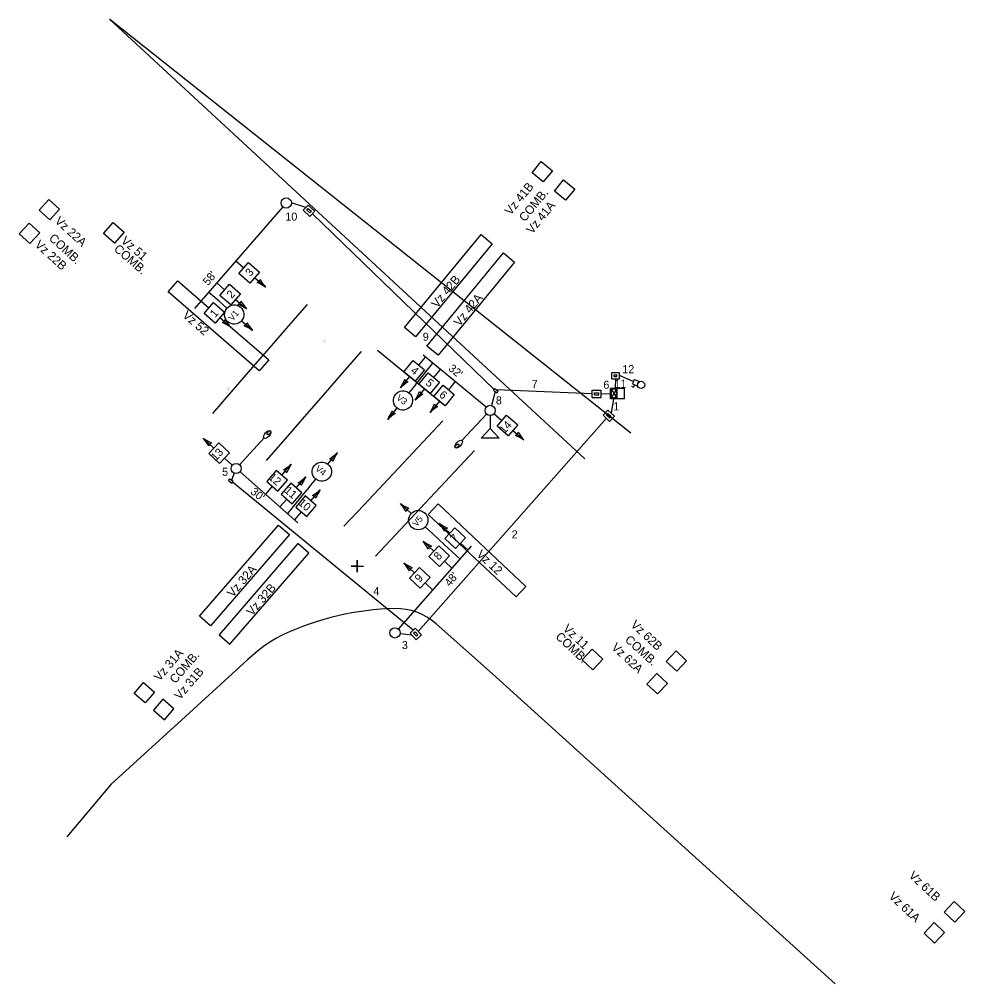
# Model space of a CAD drawing. Extents: x 973817 to 2958182, y 703625 to 1593455.
# Drawn here: x 976455 to 976847, y 705316.5 to 705716.5 of the extents above; entities that cross this region are included whole.
import ezdxf

# ---------------------------------------------------------------- set-up
doc = ezdxf.new("R2010")
doc.units = 0
for name, color, linetype in [('R_Fin Surface', 7, 'Continuous'), ('S_EDGE_PAVEMENT', 7, 'Continuous'), ('S_PAVEMENT_CROWN', 7, 'Continuous'), ('T_Conduit', 7, 'Continuous'), ('T_Detection Annot', 7, 'Continuous'), ('T_Detection Zones', 7, 'Continuous'), ('T_Drafting', 7, 'Continuous'), ('T_Indications', 7, 'Continuous'), ('T_Mast Arm', 7, 'Continuous')]:
    doc.layers.add(name, color=color, linetype=linetype)

msp = doc.modelspace()

# ---------------------------------------------------------------- linework, layer by layer
at = {"layer": 'R_Fin Surface'}
for p, q in [((976566.66, 705589.15), (976574.54, 705598.21)), ((976558.79, 705580.1), (976566.66, 705589.15)), ((976550.92, 705571.04), (976558.79, 705580.1)), ((976589.03, 705569.7), (976596.9, 705578.76)), ((976612.77, 705571.52), (976603.5, 705579.14)), ((976543.04, 705561.98), (976550.92, 705571.04)), ((976622.04, 705563.9), (976612.77, 705571.52)), ((976581.16, 705560.65), (976589.03, 705569.7)), ((976631.31, 705556.28), (976622.04, 705563.9)), ((976535.17, 705552.93), (976543.04, 705561.98)), ((976573.28, 705551.59), (976581.16, 705560.65)), ((976565.41, 705542.54), (976573.28, 705551.59)), ((976622.42, 705541.2), (976630.64, 705549.95)), ((976557.53, 705533.48), (976565.41, 705542.54)), ((976614.21, 705532.45), (976622.42, 705541.2)), ((976635.56, 705528.87), (976643.77, 705537.62)), ((976606, 705523.7), (976614.21, 705532.45)), ((976627.35, 705520.12), (976635.56, 705528.87)), ((976597.78, 705514.95), (976606, 705523.7)), ((976619.13, 705511.37), (976627.35, 705520.12)), ((976589.57, 705506.2), (976597.78, 705514.95)), ((976610.92, 705502.62), (976619.13, 705511.37)), ((976602.71, 705493.87), (976610.92, 705502.62))]:
    msp.add_line(p, q, dxfattribs=at)
for points in [[(976627.79, 705465.8), (976651.26, 705445.05), (976793.32, 705316.53)], [(976553.78, 705454.43), (976549.69, 705451), (976523.84, 705427.4), (976492.98, 705399.12), (976474.69, 705377.5)]]:
    msp.add_lwpolyline(points, dxfattribs=at)
for centre, radius, start, end in [((976613.14, 705357.1), 115, 91.2175, 115.0085), ((976611.23, 705447.08), 25, 48.5105, 91.2175), ((976585.9, 705416.11), 50, 115.3067, 129.9723)]:
    msp.add_arc(centre, radius, start, end, dxfattribs=at)
at = {"layer": 'S_EDGE_PAVEMENT'}
msp.add_lwpolyline([(976595.14, 705489.73), (976595.14, 705492.23), (976595.14, 705489.73), (976592.64, 705489.73), (976595.14, 705489.73), (976595.14, 705487.23), (976595.14, 705489.73), (976597.64, 705489.73)], dxfattribs=at)
at = {"layer": 'S_PAVEMENT_CROWN'}
for p, q in [((976492.45, 705716.47), (976689.49, 705534.24)), ((976708.53, 705544.9), (976492.53, 705716.4))]:
    msp.add_line(p, q, dxfattribs=at)
at = {"layer": 'T_Conduit'}
for p, q in [((976573.74, 705638.36), (976567.82, 705640.3)), ((976651.89, 705562.99), (976576.5, 705635.82)), ((976702.22, 705567.32), (976701.99, 705563.42)), ((976709.58, 705566.21), (976703.81, 705568.68)), ((976692.51, 705561.21), (976652.86, 705562.82)), ((976652.35, 705562.06), (976650.72, 705556.33)), ((976696.26, 705561.15), (976700.15, 705561.25)), ((976701.4, 705559.09), (976700.36, 705553.14)), ((976698.39, 705550.99), (976620.36, 705462.59)), ((976544.15, 705528.18), (976543.03, 705525.4)), ((976618.28, 705463.11), (976543.43, 705524.51)), ((976617.81, 705461.03), (976612.86, 705461.64))]:
    msp.add_line(p, q, dxfattribs=at)
at = {"layer": 'T_Detection Zones'}
for points in [[(976672.21, 705649.03), (976667.57, 705652.84), (976671.38, 705657.47), (976676.02, 705653.66)], [(976681.49, 705641.42), (976676.85, 705645.23), (976680.66, 705649.86), (976685.3, 705646.05)], [(976471.72, 705637.67), (976467.68, 705633.24), (976463.24, 705637.28), (976467.28, 705641.71)], [(976463.47, 705627.87), (976459.43, 705623.43), (976454.99, 705627.47), (976459.03, 705631.91)], [(976489.94, 705627.61), (976493.88, 705632.14), (976498.41, 705628.2), (976494.47, 705623.67)], [(976614.69, 705588.6), (976646.45, 705627.22), (976651.09, 705623.41), (976619.33, 705584.79)], [(976623.96, 705580.98), (976655.72, 705619.6), (976660.36, 705615.78), (976628.6, 705577.17)], [(976566.98, 705502.82), (976534.32, 705464.96), (976529.77, 705468.89), (976562.44, 705506.74)], [(976570.47, 705499.05), (976537.8, 705461.2), (976542.34, 705457.28), (976575.01, 705495.13)], [(976688.42, 705450.85), (976692.53, 705455.23), (976696.91, 705451.12), (976692.8, 705446.75)], [(976723.21, 705450.18), (976727.32, 705454.55), (976731.69, 705450.44), (976727.59, 705446.07)], [(976715.23, 705440.79), (976719.34, 705445.17), (976723.71, 705441.06), (976719.61, 705436.69)], [(976506.55, 705441.4), (976511.09, 705437.48), (976507.17, 705432.94), (976502.63, 705436.86)], [(976519.06, 705430.55), (976514.52, 705434.47), (976510.6, 705429.93), (976515.14, 705426.01)], [(976838.5, 705346.18), (976842.6, 705350.55), (976846.98, 705346.44), (976842.87, 705342.07)], [(976830.16, 705337.55), (976834.32, 705341.87), (976838.64, 705337.72), (976834.49, 705333.39)]]:
    msp.add_lwpolyline(points, close=True, dxfattribs=at)
for points in [[(976541.47, 705589.94), (976558.4, 705575.22), (976554.46, 705570.69), (976516.73, 705603.5), (976520.67, 705608.03), (976533.61, 705596.77)], [(976538.19, 705592.8), (976540.42, 705590.86)], [(976633.14, 705503.05), (976624.52, 705511.14), (976628.63, 705515.51), (976665.08, 705481.29), (976660.97, 705476.92), (976633.14, 705503.05)]]:
    msp.add_lwpolyline(points, dxfattribs=at)
at = {"layer": 'T_Drafting'}
for p, q in [((976572.75, 705637.29), (976574.73, 705639.43)), ((976574.73, 705639.43), (976577.49, 705636.9)), ((976572.75, 705637.29), (976575.52, 705634.75)), ((976574.17, 705637.35), (976574.79, 705638.02)), ((976574.17, 705637.35), (976575.46, 705636.16)), ((976574.79, 705638.02), (976576.08, 705636.84)), ((976575.46, 705636.16), (976576.08, 705636.84)), ((976575.52, 705634.75), (976577.49, 705636.9)), ((976648.57, 705555.61), (976622.44, 705577.16)), ((976700.62, 705570.04), (976703.81, 705570.04)), ((976700.62, 705567.32), (976700.62, 705570.04)), ((976700.62, 705567.32), (976703.81, 705567.32)), ((976701.62, 705568.32), (976701.62, 705569.04)), ((976701.62, 705569.04), (976702.81, 705569.04)), ((976701.62, 705568.32), (976702.81, 705568.32)), ((976702.81, 705568.32), (976702.81, 705569.04)), ((976703.81, 705567.32), (976703.81, 705570.04)), ((976709.98, 705567.13), (976709.19, 705565.29)), ((976709.98, 705567.13), (976711.81, 705566.34)), ((976711.81, 705566.34), (976711.03, 705564.5)), ((976651.61, 705562.63), (976652.17, 705563.35)), ((976651.61, 705562.63), (976652.99, 705561.56)), ((976652.17, 705563.35), (976653.55, 705562.28)), ((976652.99, 705561.56), (976653.55, 705562.28)), ((976692.51, 705562.61), (976696.26, 705562.61)), ((976692.51, 705559.69), (976692.51, 705562.61)), ((976696.26, 705559.69), (976696.26, 705562.61)), ((976705.89, 705563.42), (976700.15, 705563.42)), ((976700.15, 705559.09), (976700.15, 705563.42)), ((976700.48, 705559.42), (976700.48, 705563.09)), ((976702.56, 705563.09), (976700.48, 705563.09)), ((976700.48, 705559.44), (976702.56, 705563.09)), ((976700.48, 705563.09), (976702.56, 705559.42)), ((976702.56, 705559.42), (976702.56, 705563.09)), ((976702.89, 705559.09), (976702.89, 705563.42)), ((976705.89, 705559.09), (976705.89, 705563.42)), ((976708.79, 705564.37), (976709.71, 705563.97)), ((976709.19, 705565.29), (976711.03, 705564.5)), ((976710.11, 705564.89), (976709.71, 705563.97)), ((976692.51, 705559.69), (976696.26, 705559.69)), ((976693.51, 705560.69), (976693.51, 705561.61)), ((976693.51, 705561.61), (976695.26, 705561.61)), ((976693.51, 705560.69), (976695.26, 705560.69)), ((976695.26, 705560.69), (976695.26, 705561.61)), ((976705.89, 705559.09), (976700.15, 705559.09)), ((976702.56, 705559.42), (976700.48, 705559.42)), ((976697.01, 705552.26), (976698.98, 705554.41)), ((976698.98, 705554.41), (976701.74, 705551.87)), ((976648.76, 705552.7), (976638.5, 705541.75)), ((976650.26, 705552.12), (976650.26, 705546.77)), ((976697.01, 705552.26), (976699.77, 705549.72)), ((976698.42, 705552.32), (976699.04, 705552.99)), ((976698.42, 705552.32), (976699.71, 705551.14)), ((976699.04, 705552.99), (976700.33, 705551.81)), ((976699.71, 705551.14), (976700.33, 705551.81)), ((976699.77, 705549.72), (976701.74, 705551.87)), ((976646.51, 705542.77), (976650.26, 705546.77)), ((976650.26, 705546.77), (976654.01, 705542.77)), ((976546.36, 705531.74), (976556.47, 705542.83)), ((976654.01, 705542.77), (976646.51, 705542.77)), ((976541.77, 705525.22), (976542.33, 705525.95)), ((976541.77, 705525.22), (976543.15, 705524.15)), ((976542.33, 705525.95), (976543.72, 705524.87)), ((976543.15, 705524.15), (976543.72, 705524.87)), ((976617, 705461.87), (976619.1, 705463.9)), ((976618.41, 705461.85), (976619.07, 705462.48)), ((976619.07, 705462.48), (976620.29, 705461.23)), ((976619.1, 705463.9), (976621.7, 705461.2)), ((976617, 705461.87), (976619.6, 705459.17)), ((976618.41, 705461.85), (976619.63, 705460.59)), ((976619.6, 705459.17), (976621.7, 705461.2)), ((976619.63, 705460.59), (976620.29, 705461.23))]:
    msp.add_line(p, q, dxfattribs=at)
for centre, radius in [((976565.69, 705640.29), 2.13), ((976712.8, 705564.83), 1.5), ((976650.22, 705554.26), 2.13), ((976544.92, 705530.17), 2.13), ((976610.76, 705462), 2.13)]:
    msp.add_circle(centre, radius, dxfattribs=at)
for centre, major_axis in [((976557.81, 705544.3), (1.35, 1.48)), ((976558.49, 705545.04), (-0.674, -0.739)), ((976637.14, 705540.29), (-1.37, -1.46)), ((976636.45, 705539.56), (0.684, 0.73))]:
    msp.add_ellipse(centre, major_axis=major_axis, ratio=0.5, dxfattribs=at)
at = {"layer": 'T_Indications'}
for p, q in [((976548, 705613.33), (976544.72, 705616.18)), ((976540.13, 705604.27), (976536.85, 705607.12)), ((976552.58, 705609.35), (976557.13, 705605.39)), ((976537.83, 705599.52), (976533.51, 705603.28)), ((976533.57, 705596.73), (976530.29, 705599.58)), ((976537.83, 705599.52), (976541.1, 705596.67)), ((976544.7, 705600.3), (976549.26, 705596.33)), ((976538.14, 705592.75), (976542.7, 705588.79)), ((976547.14, 705591.43), (976551.72, 705587.45)), ((976620.68, 705572.98), (976623.44, 705576.34)), ((976619.27, 705564.91), (976626.44, 705573.87)), ((976626.85, 705567.89), (976629.61, 705571.25)), ((976616.83, 705568.3), (976613, 705563.63)), ((976633.02, 705562.8), (976635.78, 705566.16)), ((976619.27, 705564.91), (976616.57, 705561.53)), ((976623, 705563.21), (976619.17, 705558.54)), ((976611.57, 705555.28), (976607.78, 705550.55)), ((976629.17, 705558.12), (976625.34, 705553.45)), ((976655.06, 705549.96), (976651.78, 705552.81)), ((976535.7, 705538.66), (976531.29, 705542.79)), ((976659.63, 705545.98), (976664.19, 705542.02)), ((976540.12, 705534.51), (976543.29, 705531.54)), ((976582.96, 705531.96), (976586.8, 705536.66)), ((976563.83, 705527.38), (976567.78, 705531.95)), ((976569.84, 705522.1), (976573.79, 705526.67)), ((976559.87, 705522.8), (976557.03, 705519.51)), ((976575.16, 705522.41), (976573.4, 705520.36)), ((976575.16, 705522.41), (976577.9, 705525.76)), ((976573.4, 705520.36), (976566.15, 705511.48)), ((976575.84, 705516.81), (976579.79, 705521.38)), ((976565.88, 705517.51), (976563.04, 705514.22)), ((976617.51, 705511.51), (976613.09, 705515.66)), ((976571.88, 705512.22), (976569.04, 705508.93)), ((976633.46, 705503.4), (976629.06, 705507.54)), ((976626.5, 705503.08), (976623.34, 705506.04)), ((976626.84, 705495.9), (976622.44, 705500.04)), ((976637.88, 705499.25), (976641.05, 705496.28)), ((976618.89, 705486.91), (976614.49, 705491.04)), ((976631.26, 705491.76), (976634.43, 705488.78)), ((976623.31, 705482.76), (976626.48, 705479.79))]:
    msp.add_line(p, q, dxfattribs=at)
for points in [[(976554.57, 705611.63), (976550.59, 705607.07), (976546.01, 705611.04), (976549.99, 705615.61)], [(976546.69, 705602.58), (976542.71, 705598.01), (976538.14, 705601.99), (976542.12, 705606.56)], [(976540.13, 705595.03), (976536.15, 705590.46), (976531.58, 705594.44), (976535.56, 705599.01)], [(976619.17, 705566.37), (976614.49, 705570.23), (976618.34, 705574.91), (976623.02, 705571.06)], [(976625.34, 705561.28), (976620.66, 705565.14), (976624.51, 705569.82), (976629.19, 705565.97)], [(976631.51, 705556.19), (976626.84, 705560.05), (976630.68, 705564.73), (976635.36, 705560.88)], [(976661.63, 705548.26), (976657.64, 705543.7), (976653.07, 705547.67), (976657.05, 705552.24)], [(976533.62, 705536.45), (976537.77, 705540.86), (976542.19, 705536.72), (976538.04, 705532.3)], [(976566.13, 705525.41), (976561.54, 705529.36), (976557.58, 705524.77), (976562.17, 705520.82)], [(976572.13, 705520.12), (976567.54, 705524.07), (976563.58, 705519.49), (976568.17, 705515.53)], [(976578.14, 705514.83), (976573.55, 705518.79), (976569.59, 705514.2), (976574.18, 705510.25)], [(976631.39, 705501.2), (976635.54, 705505.61), (976639.96, 705501.46), (976635.8, 705497.05)], [(976624.76, 705493.7), (976628.92, 705498.11), (976633.33, 705493.96), (976629.18, 705489.55)], [(976616.82, 705484.7), (976620.97, 705489.12), (976625.39, 705484.97), (976621.24, 705480.56)]]:
    msp.add_lwpolyline(points, close=True, dxfattribs=at)
msp.add_lwpolyline([(976626.5, 705503.08), (976631.17, 705498.69), (976637.73, 705492.53)], dxfattribs=at)
for centre, major_axis, ratio, start_param, end_param in [((976553.16, 705608.84), (1.62, -0.2), 0.998761, 5.132551, 6.244232), ((976541.33, 705580.55), (-29.26, 3.57), 0.998761, 4.267839, 4.402894), ((976579.59, 705624.45), (29.26, -3.57), 0.998761, 3.832296, 3.967352), ((976545.29, 705599.79), (1.62, -0.2), 0.998761, 5.132551, 6.244232), ((976533.46, 705571.49), (-29.26, 3.57), 0.998761, 4.267839, 4.402894), ((976571.72, 705615.39), (29.26, -3.57), 0.998761, 3.832296, 3.967352), ((976538.72, 705592.24), (1.62, -0.2), 0.998761, 5.132551, 6.244232), ((976526.9, 705563.94), (-29.26, 3.57), 0.998761, 4.267839, 4.402894), ((976565.15, 705607.84), (29.26, -3.57), 0.998761, 3.832296, 3.967352), ((976547.74, 705590.9), (1.23, -1.07), 0.999186, 5.727365, 6.839046), ((976574.15, 705606.52), (22.24, -19.34), 0.999186, 4.42711, 4.562166), ((976535.94, 705562.58), (-22.24, 19.34), 0.999186, 4.862653, 4.997709), ((976587.72, 705578.74), (2.89, 29.33), 0.998816, 4.272384, 4.407439), ((976616.34, 705567.7), (-0.16, -1.62), 0.998816, 5.137096, 6.248777), ((976632.67, 705541.72), (-2.89, -29.33), 0.998816, 3.836841, 3.971897), ((976593.89, 705573.65), (2.89, 29.33), 0.998816, 4.272384, 4.407439), ((976638.84, 705536.63), (-2.89, -29.33), 0.998816, 3.836841, 3.971897), ((976622.51, 705562.61), (-0.16, -1.62), 0.998816, 5.137096, 6.248777), ((976600.07, 705568.56), (2.89, 29.33), 0.998816, 4.272384, 4.407439), ((976645.02, 705531.54), (-2.89, -29.33), 0.998816, 3.836841, 3.971897), ((976628.68, 705557.52), (-0.16, -1.62), 0.998816, 5.137096, 6.248777), ((976582.29, 705565.29), (18.41, 23.01), 0.999186, 4.862665, 4.997721), ((976627.76, 705528.92), (-18.41, -23.01), 0.999186, 4.427123, 4.562178), ((976611.07, 705554.66), (-1.02, -1.27), 0.999186, 5.727378, 6.839059), ((976508.13, 705524.6), (-29.1, 4.68), 0.998761, 3.832296, 3.967352), ((976548.03, 705567.02), (29.1, -4.68), 0.998761, 4.267839, 4.402894), ((976660.22, 705545.47), (1.62, -0.2), 0.998761, 5.132551, 6.244232), ((976648.39, 705517.18), (-29.26, 3.57), 0.998761, 4.267839, 4.402894), ((976686.65, 705561.08), (29.26, -3.57), 0.998761, 3.832296, 3.967352), ((976535.13, 705539.19), (-1.61, 0.26), 0.998761, 5.132551, 6.244232), ((976567.03, 705558.49), (18.64, 22.83), 0.999186, 4.42711, 4.562166), ((976583.47, 705532.58), (1.03, 1.26), 0.999186, 5.727365, 6.839046), ((976612.14, 705521.66), (-18.64, -22.83), 0.999186, 4.862653, 4.997709), ((976548.6, 705554.29), (28.41, 7.83), 0.998816, 5.017339, 5.152394), ((976592.72, 705516.29), (-28.41, -7.83), 0.998816, 5.452881, 5.587937), ((976564.34, 705527.97), (1.57, 0.43), 0.998816, 0.034408, 1.146089), ((976554.61, 705549.01), (28.41, 7.83), 0.998816, 5.017339, 5.152394), ((976598.73, 705511), (-28.41, -7.83), 0.998816, 5.452881, 5.587937), ((976570.34, 705522.68), (1.57, 0.43), 0.998816, 0.034408, 1.146089), ((976560.61, 705543.72), (28.41, 7.83), 0.998816, 5.017339, 5.152394), ((976576.35, 705517.4), (1.57, 0.43), 0.998816, 0.034408, 1.146089), ((976604.73, 705505.72), (-28.41, -7.83), 0.998816, 5.452881, 5.587937), ((976629.82, 705539.92), (-27.18, -11.4), 0.999533, 0.569949, 0.705004), ((976589.93, 705497.44), (27.18, 11.4), 0.999533, 0.134406, 0.269462), ((976616.93, 705512.06), (-1.5, -0.63), 0.999533, 4.576253, 5.687935), ((976605.89, 705489.36), (-29.1, 4.7), 0.998761, 3.832296, 3.967352), ((976645.81, 705531.75), (29.1, -4.7), 0.998761, 4.267839, 4.402894), ((976632.9, 705503.93), (-1.61, 0.26), 0.998761, 5.132551, 6.244232), ((976599.27, 705481.85), (-29.1, 4.68), 0.998761, 3.832296, 3.967352), ((976639.17, 705524.26), (29.1, -4.68), 0.998761, 4.267839, 4.402894), ((976626.28, 705496.43), (-1.61, 0.26), 0.998761, 5.132551, 6.244232), ((976591.33, 705472.85), (-29.1, 4.68), 0.998761, 3.832296, 3.967352), ((976631.22, 705515.27), (29.1, -4.68), 0.998761, 4.267839, 4.402894), ((976618.33, 705487.44), (-1.61, 0.26), 0.998761, 5.132551, 6.244232)]:
    msp.add_ellipse(centre, major_axis=major_axis, ratio=ratio, start_param=start_param, end_param=end_param, dxfattribs=at)
for centre, major_axis, ratio in [((976544.12, 705594.05), (3.02, -2.62), 0.999186), ((976614.07, 705558.41), (-2.5, -3.12), 0.999186), ((976580.43, 705528.86), (2.53, 3.1), 0.999186), ((976620.42, 705508.78), (3.69, 1.55), 0.999533)]:
    msp.add_ellipse(centre, major_axis=major_axis, ratio=ratio, dxfattribs=at)
at = {"layer": 'T_Mast Arm'}
for p, q in [((976564.29, 705638.68), (976527.63, 705596.52)), ((976546.52, 705528.76), (976570.44, 705507.7)), ((976612.17, 705463.59), (976642.54, 705497.97))]:
    msp.add_line(p, q, dxfattribs=at)

# ---------------------------------------------------------------- texts
for s, p in [('N=705583.16  ', (976580.83, 705583.07)), ('E=976580.73  ', (976581.01, 705582.91)), ('Sta=35+73.93 ', (976581.19, 705582.75)), ("Off=25.34' ", (976581.36, 705582.58)), ('7.72m ', (976581.54, 705582.42)), ('N=705563.21  ', (976540.91, 705563.11)), ('E=976540.81  ', (976541.09, 705562.95)), ('Sta=35+90.15 ', (976541.27, 705562.79)), ("Off=16.24' ", (976541.44, 705562.63)), ('4.95m ', (976541.62, 705562.47)), ('N=705536.54  ', (976586.36, 705536.45)), ('E=976586.25  ', (976586.53, 705536.29)), ('Sta=35+38.56 ', (976586.71, 705536.13)), ("Off=5.53' ", (976586.89, 705535.97)), ('1.69m ', (976587.07, 705535.8)), ('N=705515.11  ', (976612.53, 705515.02)), ('E=976612.42  ', (976612.71, 705514.86)), ('Sta=35+04.78 ', (976612.88, 705514.7)), ("Off=3.86' ", (976613.06, 705514.54)), ('1.18m ', (976613.24, 705514.38))]:
    msp.add_text(s, height=0.14, rotation=47.8686).set_placement(p)
at = {"layer": 'S_PAVEMENT_CROWN'}
for s, p in [('10', (976565.31, 705632.97)), ('9', (976622.28, 705583.16)), ('12', (976705.02, 705569.71)), ('7', (976667.45, 705563.57)), ('6', (976697.16, 705563.26)), ('11', (976701.78, 705563.67)), ('8', (976652.6, 705556.76)), ('1', (976701.24, 705554.27)), ('5', (976539.07, 705527.17)), ('2', (976659.14, 705501.2)), ('4', (976601.8, 705477.65)), ('3', (976613.62, 705455.31))]:
    msp.add_text(s, height=3.33, dxfattribs=at).set_placement(p)
at = {"layer": 'T_Detection Annot'}
for s, rotation, p in [('Vz 41B', 50.6653, (976658.67, 705634.97)), ('COMB.', 50.6653, (976664.62, 705632.25)), ('Vz 41A', 50.6653, (976667.63, 705627.17)), ('Vz 22A', 317.6645, (976469.43, 705632.4)), ('COMB.', 317.6645, (976467, 705625.27)), ('Vz 51', 318.993, (976496.9, 705624.17)), ('Vz 22B', 317.6645, (976461.18, 705622.59)), ('COMB.', 318.993, (976493.94, 705620.77)), ('Vz 42B', 50.6653, (976628.26, 705596.44)), ('Vz 42A', 50.6653, (976637.53, 705588.82)), ('Vz 52', 318.993, (976522.4, 705593.23)), ('Vz 12', 316.8083, (976644.31, 705494.2)), ('Vz 32A', 49.2058, (976543.52, 705476.49)), ('Vz 32B', 49.2058, (976551.55, 705468.8)), ('Vz 62B', 316.8083, (976708.22, 705465.01)), ('Vz 11', 316.8083, (976680.14, 705463.38)), ('COMB.', 316.8083, (976677.05, 705460.09)), ('Vz 62A', 316.8083, (976700.24, 705455.63)), ('COMB.', 317.6645, (976705.82, 705458.75)), ('Vz 31A', 49.2058, (976513.14, 705441.72)), ('COMB.', 49.2058, (976519.68, 705440.73)), ('Vz 31B', 49.2058, (976521.6, 705434)), ('Vz 61B', 316.8083, (976823.51, 705361.01)), ('Vz 61A', 316.8083, (976815.2, 705352.36))]:
    msp.add_text(s, height=3.6, rotation=rotation, dxfattribs=at).set_placement(p)
at = {"layer": 'T_Indications'}
for s, height, rotation, p in [("58'", 3.33, 50.3975, (976533.3, 705605.82)), ('3', 3.33, 48.931, (976550.84, 705609.59)), ('2', 3.33, 48.931, (976543.11, 705600.46)), ('1', 3.33, 48.931, (976536.19, 705592.56)), ('V1', 2.66, 50.0757, (976543.45, 705591.14)), ('4', 3.33, 320.3844, (976616.99, 705570.27)), ("32'", 3.33, 320.3975, (976632.62, 705571.21)), ('5', 3.33, 320.3844, (976623.16, 705565.18)), ('6', 3.33, 320.3844, (976628.77, 705560.23)), ('V3', 2.66, 322.4194, (976611.12, 705559.05)), ('14', 3.33, 48.931, (976656.17, 705544.35)), ('13', 3.33, 46.7585, (976536.48, 705533.1)), ('V4', 2.66, 321.8548, (976577.49, 705529.63)), ('12', 3.33, 319.423, (976558.03, 705526.09)), ("30'", 3.33, 320.3975, (976550.58, 705520.09)), ('11', 3.33, 319.423, (976564.61, 705520.59)), ('10', 3.33, 319.423, (976570.37, 705515.51)), ('V5', 2.66, 50.0757, (976619.75, 705505.87)), ('7', 3.33, 46.721, (976635.78, 705499.27)), ('8', 3.33, 46.7524, (976628.88, 705491.92)), ('9', 3.33, 46.7585, (976620.99, 705482.75)), ("48'", 3.33, 50.3975, (976633.51, 705480.98))]:
    msp.add_text(s, height=height, rotation=rotation, dxfattribs=at).set_placement(p)

doc.saveas('drawing.dxf')
